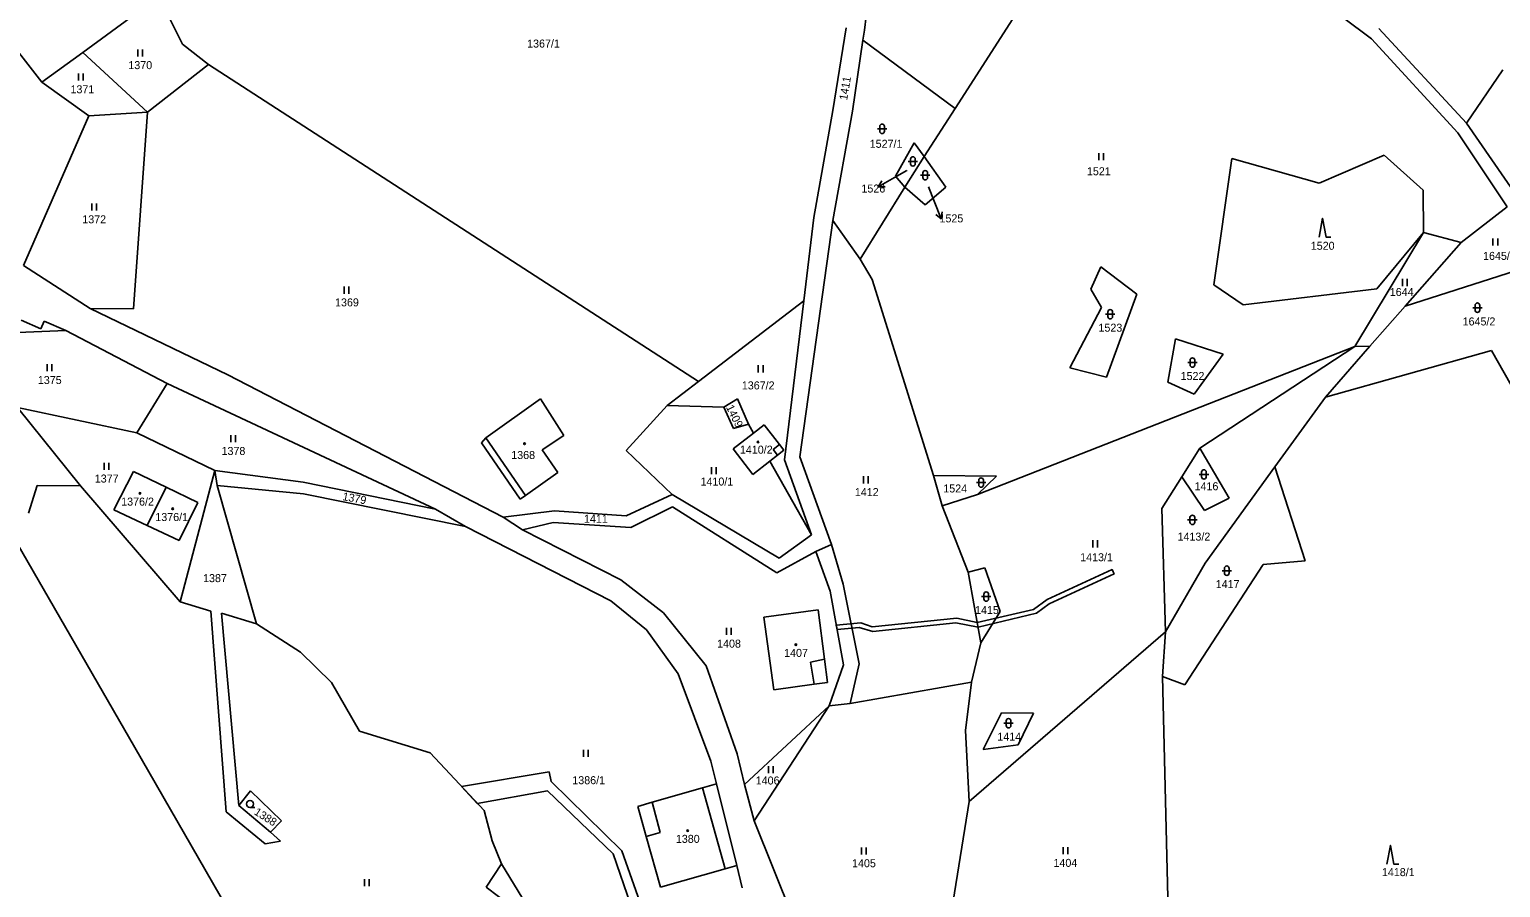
# Model space of a CAD drawing. Extents: x -670359 to -660124, y -978807 to -970072.
# Drawn here: x -669575.5 to -669263, y -978442.6 to -978260.3 of the extents above; entities that cross this region are included whole.
import ezdxf

# ---------------------------------------------------------------- set-up
doc = ezdxf.new("R2010")
doc.units = 0
for name, color, linetype in [('Hranice kat_území', 7, 'Continuous'), ('Hranice parcel', 7, 'Continuous'), ('Parcelní čísla', 7, 'Continuous'), ('Vnitřní kresba', 7, 'Continuous'), ('Věcná břemena k části', 7, 'Continuous'), ('Značky budov', 7, 'Continuous'), ('Značky kultur', 7, 'Continuous')]:
    doc.layers.add(name, color=color, linetype=linetype)

msp = doc.modelspace()

# ---------------------------------------------------------------- linework, layer by layer
at = {"layer": 'Hranice kat_území'}
for points in [[(-669579.21, -978367.53), (-669553.11, -978412.89)], [(-669553.11, -978412.89), (-669532.01, -978449.57)]]:
    msp.add_lwpolyline(points, dxfattribs=at)
at = {"layer": 'Hranice parcel'}
for p, q in [((-669411.05, -978318), (-669408.91, -978300.27)), ((-669433.38, -978335.12), (-669411.05, -978318)), ((-669411.05, -978318), (-669415.14, -978351.79))]:
    msp.add_line(p, q, dxfattribs=at)
for points in [[(-669388.24, -978177.08), (-669398.17, -978260.47)], [(-669572.87, -978271.54), (-669624.52, -978205.08)], [(-669343.73, -978222.27), (-669378.91, -978277.09)], [(-669290.44, -978262.28), (-669308.63, -978248.64)], [(-669548.02, -978253.34), (-669564.16, -978265.18)], [(-669543.01, -978263.47), (-669548.02, -978253.34)], [(-669402.01, -978259.95), (-669404.83, -978277.52)], [(-669398.17, -978260.47), (-669398.48, -978262.57)], [(-669288.9, -978260.13), (-669270.3, -978280.25)], [(-669537.45, -978267.77), (-669543.01, -978263.47)], [(-669400.67, -978277.64), (-669398.48, -978262.57)], [(-669398.48, -978262.57), (-669378.91, -978277.09)], [(-669290.44, -978262.28), (-669272.16, -978282.31)], [(-669564.16, -978265.18), (-669572.87, -978271.54)], [(-669550.44, -978277.86), (-669564.16, -978265.18)], [(-669537.45, -978267.77), (-669550.44, -978277.86)], [(-669433.38, -978335.12), (-669537.45, -978267.77)], [(-669270.3, -978280.25), (-669262.58, -978268.89)], [(-669562.88, -978278.68), (-669572.87, -978271.54)], [(-669576.72, -978310.45), (-669562.88, -978278.68)], [(-669550.44, -978277.86), (-669562.88, -978278.68)], [(-669550.44, -978277.86), (-669553.36, -978319.66)], [(-669404.83, -978277.52), (-669408.91, -978300.27)], [(-669400.67, -978277.64), (-669404.84, -978300.87)], [(-669385.48, -978287.32), (-669378.91, -978277.09)], [(-669272.16, -978282.31), (-669261.68, -978298.02)], [(-669270.3, -978280.25), (-669259.5, -978295.8)], [(-669387.61, -978284.42), (-669391.53, -978291.5)], [(-669385.48, -978287.32), (-669387.61, -978284.42)], [(-669385.48, -978287.32), (-669389.56, -978293.84)], [(-669385.48, -978287.32), (-669380.83, -978293.85)], [(-669320.09, -978287.71), (-669323.97, -978314.54)], [(-669301.57, -978292.95), (-669320.09, -978287.71)], [(-669287.74, -978287.02), (-669301.57, -978292.95)], [(-669279.5, -978294.47), (-669287.74, -978287.02)], [(-669391.53, -978291.5), (-669389.56, -978293.84)], [(-669389.56, -978293.84), (-669399.08, -978309.09)], [(-669385.27, -978297.56), (-669389.56, -978293.84)], [(-669380.83, -978293.85), (-669385.27, -978297.56)], [(-669279.43, -978303.43), (-669279.5, -978294.47)], [(-669261.68, -978298.02), (-669271.45, -978305.59)], [(-669404.84, -978300.87), (-669411.85, -978351.11)], [(-669404.84, -978300.87), (-669399.08, -978309.09)], [(-669279.43, -978303.43), (-669294.02, -978327.66)], [(-669289.32, -978315.4), (-669279.43, -978303.43)], [(-669271.45, -978305.59), (-669279.43, -978303.43)], [(-669271.45, -978305.59), (-669283.33, -978319.11)], [(-669562.62, -978319.59), (-669576.72, -978310.45)], [(-669399.08, -978309.09), (-669396.49, -978313.44)], [(-669350.08, -978315.46), (-669347.95, -978310.76)], [(-669347.95, -978310.76), (-669340.33, -978316.53)], [(-669283.33, -978319.11), (-669252.6, -978309.23)], [(-669396.49, -978313.44), (-669383.48, -978355.09)], [(-669347.8, -978319.4), (-669350.08, -978315.46)], [(-669340.33, -978316.53), (-669346.76, -978334.21)], [(-669323.97, -978314.54), (-669317.7, -978318.85)], [(-669317.7, -978318.85), (-669289.32, -978315.4)], [(-669533.35, -978333.71), (-669562.62, -978319.59)], [(-669553.36, -978319.66), (-669562.62, -978319.59)], [(-669354.5, -978332.21), (-669347.8, -978319.4)], [(-669290.81, -978327.62), (-669283.33, -978319.11)], [(-669573.09, -978323.91), (-669577.23, -978322.1)], [(-669572.37, -978322.26), (-669573.09, -978323.91)], [(-669567.79, -978324.26), (-669572.37, -978322.26)], [(-669567.79, -978324.26), (-669588.32, -978325.13)], [(-669546.24, -978335.54), (-669567.79, -978324.26)], [(-669333.72, -978335.23), (-669332.1, -978326.05)], [(-669332.1, -978326.05), (-669321.97, -978329.28)], [(-669294.02, -978327.66), (-669374.15, -978359.11)], [(-669321.97, -978329.28), (-669328.14, -978337.77)], [(-669326.9, -978349.3), (-669294.02, -978327.66)], [(-669290.81, -978327.62), (-669300.21, -978338.47)], [(-669300.21, -978338.47), (-669264.97, -978328.54)], [(-669294.02, -978327.66), (-669290.81, -978327.62)], [(-669264.97, -978328.54), (-669259.62, -978338.03)], [(-669346.76, -978334.21), (-669354.5, -978332.21)], [(-669552.68, -978345.99), (-669546.24, -978335.54)], [(-669489.22, -978362.27), (-669546.24, -978335.54)], [(-669474.91, -978363.94), (-669533.35, -978333.71)], [(-669440.07, -978340.24), (-669433.38, -978335.12)], [(-669328.14, -978337.77), (-669333.72, -978335.23)], [(-669478.57, -978347.11), (-669466.96, -978338.79)], [(-669466.96, -978338.79), (-669461.99, -978346.57)], [(-669425.09, -978338.81), (-669427.99, -978340.53)], [(-669422.75, -978344.19), (-669425.09, -978338.81)], [(-669300.21, -978338.47), (-669311.02, -978353.24)], [(-669552.68, -978345.99), (-669578, -978340.67)], [(-669578, -978340.67), (-669564.65, -978357.3)], [(-669440.07, -978340.24), (-669448.74, -978349.75)], [(-669427.99, -978340.53), (-669440.07, -978340.24)], [(-669425.96, -978345.12), (-669427.99, -978340.53)], [(-669422.75, -978344.19), (-669425.96, -978345.12)], [(-669422.75, -978344.19), (-669421.68, -978346.06)], [(-669419.44, -978344.32), (-669421.68, -978346.06)], [(-669416.17, -978348.51), (-669419.44, -978344.32)], [(-669536.12, -978354), (-669552.68, -978345.99)], [(-669479.46, -978348.14), (-669478.57, -978347.11)], [(-669471.26, -978360.14), (-669479.46, -978348.14)], [(-669461.99, -978346.57), (-669466.59, -978349.64)], [(-669421.68, -978346.06), (-669426.02, -978349.45)], [(-669466.59, -978349.64), (-669463.24, -978354.47)], [(-669448.74, -978349.75), (-669438.99, -978359.09)], [(-669426.02, -978349.45), (-669421.82, -978354.85)], [(-669418.27, -978352.06), (-669416.59, -978350.73)], [(-669416.59, -978350.73), (-669415.25, -978349.69)], [(-669415.25, -978349.69), (-669416.17, -978348.51)], [(-669411.85, -978351.11), (-669405.17, -978369.74)], [(-669330.73, -978355.34), (-669326.9, -978349.3)], [(-669326.9, -978349.3), (-669320.69, -978359.93)], [(-669557.58, -978362.41), (-669553.41, -978354.26)], [(-669553.41, -978354.26), (-669546.47, -978357.59)], [(-669536.12, -978354), (-669543.46, -978381.92)], [(-669535.59, -978357.21), (-669536.12, -978354)], [(-669536.12, -978354), (-669517.33, -978356.53)], [(-669463.24, -978354.47), (-669470.13, -978359.36)], [(-669421.82, -978354.85), (-669418.27, -978352.06)], [(-669409.39, -978367.69), (-669418.27, -978352.06)], [(-669415.14, -978351.79), (-669409.39, -978367.69)], [(-669311.02, -978353.24), (-669325.8, -978373.71)], [(-669311.02, -978353.24), (-669304.58, -978373.22)], [(-669573.85, -978357.2), (-669575.68, -978363.1)], [(-669564.65, -978357.3), (-669573.85, -978357.2)], [(-669543.46, -978381.92), (-669564.65, -978357.3)], [(-669546.47, -978357.59), (-669550.47, -978365.74)], [(-669546.47, -978357.59), (-669539.71, -978360.84)], [(-669535.59, -978357.21), (-669517.28, -978359.01)], [(-669527.26, -978386.57), (-669535.59, -978357.21)], [(-669517.33, -978356.53), (-669489.22, -978362.27)], [(-669383.48, -978355.09), (-669381.62, -978361.51)], [(-669370.11, -978355.24), (-669383.48, -978355.09)], [(-669374.15, -978359.11), (-669370.11, -978355.24)], [(-669335.02, -978362.1), (-669330.73, -978355.34)], [(-669325.92, -978362.51), (-669330.73, -978355.34)], [(-669517.28, -978359.01), (-669482.85, -978365.94)], [(-669470.13, -978359.36), (-669471.26, -978360.14)], [(-669438.99, -978359.09), (-669448.73, -978363.67)], [(-669416.24, -978372.66), (-669438.99, -978359.09)], [(-669374.15, -978359.11), (-669381.62, -978361.51)], [(-669320.69, -978359.93), (-669325.92, -978362.51)], [(-669550.47, -978365.74), (-669557.58, -978362.41)], [(-669539.71, -978360.84), (-669543.68, -978368.92)], [(-669482.85, -978365.94), (-669489.22, -978362.27)], [(-669464.01, -978362.62), (-669474.91, -978363.94)], [(-669470.77, -978366.63), (-669474.91, -978363.94)], [(-669448.73, -978363.67), (-669464.01, -978362.62)], [(-669438.94, -978361.77), (-669447.79, -978366.16)], [(-669416.76, -978375.77), (-669438.94, -978361.77)], [(-669381.62, -978361.51), (-669376.09, -978375.65)], [(-669334.2, -978388.3), (-669335.02, -978362.1)], [(-669543.68, -978368.92), (-669550.47, -978365.74)], [(-669452.04, -978381.71), (-669482.85, -978365.94)], [(-669464.27, -978365.1), (-669470.77, -978366.63)], [(-669449.91, -978377.25), (-669470.77, -978366.63)], [(-669447.79, -978366.16), (-669464.27, -978365.1)], [(-669409.39, -978367.69), (-669416.24, -978372.66)], [(-669405.17, -978369.74), (-669408.46, -978371.22)], [(-669408.46, -978371.22), (-669416.76, -978375.77)], [(-669408.46, -978371.22), (-669405.43, -978379.65)], [(-669304.58, -978373.22), (-669313.48, -978374)], [(-669372.56, -978374.73), (-669376.09, -978375.65)], [(-669376.09, -978375.65), (-669373.45, -978390.63)], [(-669369.29, -978383.96), (-669372.56, -978374.73)], [(-669325.8, -978373.71), (-669334.2, -978388.3)], [(-669313.48, -978374), (-669330.08, -978399.58)], [(-669440.86, -978384.23), (-669449.91, -978377.25)], [(-669536.99, -978383.91), (-669543.46, -978381.92)], [(-669444.42, -978387.87), (-669452.04, -978381.71)], [(-669405.43, -978379.65), (-669402.63, -978395.28)], [(-669533.68, -978426.58), (-669536.99, -978383.91)], [(-669527.26, -978386.57), (-669534.68, -978384.33)], [(-669534.68, -978384.33), (-669531.02, -978425.17)], [(-669431.77, -978395.52), (-669440.86, -978384.23)], [(-669419.5, -978385.18), (-669407.95, -978383.66)], [(-669417.42, -978400.64), (-669419.5, -978385.18)], [(-669407.95, -978383.66), (-669406.62, -978394.11)], [(-669373.45, -978390.63), (-669369.29, -978383.96)], [(-669517.95, -978392.59), (-669527.26, -978386.57)], [(-669437.71, -978397.22), (-669444.42, -978387.87)], [(-669334.2, -978388.3), (-669375.91, -978424.37)], [(-669334.86, -978397.77), (-669334.2, -978388.3)], [(-669373.45, -978390.63), (-669375.38, -978399.01)], [(-669511.3, -978399.06), (-669517.95, -978392.59)], [(-669406.62, -978394.11), (-669405.99, -978399.06)], [(-669430.79, -978415.77), (-669437.71, -978397.22)], [(-669425.17, -978414.23), (-669431.77, -978395.52)], [(-669402.63, -978395.28), (-669405.61, -978404.04)], [(-669330.08, -978399.58), (-669334.86, -978397.77)], [(-669334.86, -978397.77), (-669333.58, -978450.65)], [(-669505.4, -978409.44), (-669511.3, -978399.06)], [(-669408.84, -978399.45), (-669417.42, -978400.64)], [(-669405.99, -978399.06), (-669408.84, -978399.45)], [(-669375.38, -978399.01), (-669401.2, -978403.53)], [(-669376.69, -978409.24), (-669375.38, -978399.01)], [(-669405.61, -978404.04), (-669423.63, -978420.73)], [(-669405.61, -978404.04), (-669421.55, -978428.43)], [(-669401.2, -978403.53), (-669405.61, -978404.04)], [(-669372.97, -978413.27), (-669369.04, -978405.48)], [(-669369.04, -978405.48), (-669362.24, -978405.55)], [(-669362.24, -978405.55), (-669365.51, -978412.32)], [(-669490.4, -978414.01), (-669505.4, -978409.44)], [(-669375.91, -978424.37), (-669376.69, -978409.24)], [(-669365.51, -978412.32), (-669372.97, -978413.27)], [(-669478.93, -978426.29), (-669490.4, -978414.01)], [(-669429.59, -978420.58), (-669430.79, -978415.77)], [(-669423.63, -978420.73), (-669425.17, -978414.23)], [(-669531.02, -978425.17), (-669528.51, -978422.07)], [(-669528.51, -978422.07), (-669521.93, -978428.46)], [(-669432.53, -978421.43), (-669443.21, -978424.51)], [(-669429.59, -978420.58), (-669432.53, -978421.43)], [(-669425.28, -978437.98), (-669429.59, -978420.58)], [(-669421.55, -978428.43), (-669423.63, -978420.73)], [(-669524.28, -978430.84), (-669531.02, -978425.17)], [(-669477.23, -978432.7), (-669478.93, -978426.29)], [(-669443.21, -978424.51), (-669446.28, -978425.4)], [(-669446.28, -978425.4), (-669444.48, -978431.78)], [(-669375.91, -978424.37), (-669381.83, -978461.38)], [(-669525.43, -978433.38), (-669533.68, -978426.58)], [(-669521.93, -978428.46), (-669524.28, -978430.84)], [(-669413.37, -978448.91), (-669421.55, -978428.43)], [(-669524.28, -978430.84), (-669522.14, -978432.78)], [(-669444.48, -978431.78), (-669441.44, -978442.57)], [(-669522.14, -978432.78), (-669525.43, -978433.38)], [(-669475.2, -978437.61), (-669477.23, -978432.7)], [(-669478.46, -978442.53), (-669475.2, -978437.61)], [(-669475.2, -978437.61), (-669469.93, -978446.3)], [(-669441.44, -978442.57), (-669427.75, -978438.68)], [(-669427.75, -978438.68), (-669425.28, -978437.98)], [(-669424.11, -978442.72), (-669425.28, -978437.98)], [(-669470.64, -978448.51), (-669478.46, -978442.53)]]:
    msp.add_lwpolyline(points, dxfattribs=at)
at = {"layer": 'Parcelní čísla'}
for p, q in [((-669389.18, -978290.28), (-669391.77, -978291.77)), ((-669393.74, -978293.76), (-669395.24, -978293.76)), ((-669384.52, -978293.78), (-669383.32, -978296.81)), ((-669381.63, -978299.04), (-669381.84, -978300.53))]:
    msp.add_line(p, q, dxfattribs=at)
for points in [[(-669391.77, -978291.77), (-669395.24, -978293.76), (-669394.48, -978292.46)], [(-669383.32, -978296.81), (-669381.84, -978300.53), (-669383.02, -978299.6)]]:
    msp.add_lwpolyline(points, dxfattribs=at)
at = {"layer": 'Vnitřní kresba'}
for points in [[(-669478.57, -978347.11), (-669470.13, -978359.36)], [(-669416.17, -978348.51), (-669417.51, -978349.55)], [(-669417.51, -978349.55), (-669416.59, -978350.73)], [(-669402.69, -978378.16), (-669405.17, -978369.74)], [(-669399.27, -978395.07), (-669402.69, -978378.16)], [(-669409.59, -978394.72), (-669406.62, -978394.11)], [(-669408.84, -978399.45), (-669409.59, -978394.72)], [(-669401.2, -978403.53), (-669399.27, -978395.07)], [(-669432.53, -978421.43), (-669427.75, -978438.68)], [(-669443.21, -978424.51), (-669441.55, -978430.93)], [(-669441.55, -978430.93), (-669444.48, -978431.78)]]:
    msp.add_lwpolyline(points, dxfattribs=at)
at = {"layer": 'Věcná břemena k části'}
for p, q in [((-669483.73, -978421.15), (-669465.12, -978418.04)), ((-669465.12, -978418.04), (-669464.66, -978420.07)), ((-669464.66, -978420.07), (-669449.65, -978434.83)), ((-669480.37, -978424.75), (-669483.73, -978421.15)), ((-669465.46, -978422.11), (-669480.37, -978424.75)), ((-669451.54, -978435.49), (-669465.46, -978422.11)), ((-669447.74, -978446.35), (-669451.54, -978435.49)), ((-669449.65, -978434.83), (-669445.86, -978445.69))]:
    msp.add_line(p, q, dxfattribs=at)
for points in [[(-669404.14, -978386.88), (-669398.94, -978386.4), (-669396.5, -978387.26), (-669378.51, -978385.42), (-669374.21, -978386.3), (-669362.22, -978383.56), (-669359.32, -978381.42), (-669346.46, -978375.5), (-669345.55, -978375.08), (-669345.34, -978375.53), (-669345.14, -978375.99), (-669346.04, -978376.4), (-669358.9, -978382.32), (-669361.64, -978384.36), (-669373.99, -978387.28), (-669378.71, -978386.4), (-669396.4, -978388.26), (-669399.26, -978387.36), (-669403.96, -978387.83)], [(-669403.96, -978387.83), (-669404.14, -978386.88)]]:
    msp.add_lwpolyline(points, dxfattribs=at)
at = {"layer": 'Značky budov'}
for centre in [(-669470.33, -978348.33), (-669420.76, -978347.95), (-669552, -978358.88), (-669545.07, -978362.16), (-669412.71, -978391.03), (-669435.7, -978430.54)]:
    msp.add_circle(centre, 0.175, dxfattribs=at)
at = {"layer": 'Značky kultur'}
for p, q in [((-669552.48, -978264.54), (-669552.48, -978266.04)), ((-669551.48, -978266.04), (-669551.48, -978264.54)), ((-669565.09, -978269.67), (-669565.09, -978271.17)), ((-669564.09, -978271.17), (-669564.09, -978269.67)), ((-669395.39, -978281.43), (-669393.39, -978281.43)), ((-669394.89, -978280.93), (-669394.89, -978281.93)), ((-669393.89, -978280.93), (-669393.89, -978281.93)), ((-669388.86, -978288.35), (-669386.86, -978288.35)), ((-669388.36, -978287.85), (-669388.36, -978288.85)), ((-669387.36, -978287.85), (-669387.36, -978288.85)), ((-669348.4, -978286.6), (-669348.4, -978288.1)), ((-669347.4, -978288.1), (-669347.4, -978286.6)), ((-669386.25, -978291.29), (-669384.25, -978291.29)), ((-669385.75, -978290.79), (-669385.75, -978291.79)), ((-669384.75, -978290.79), (-669384.75, -978291.79)), ((-669562.26, -978297.3), (-669562.26, -978298.8)), ((-669561.26, -978298.8), (-669561.26, -978297.3)), ((-669264.66, -978304.74), (-669264.66, -978306.24)), ((-669263.66, -978306.24), (-669263.66, -978304.74)), ((-669283.89, -978313.33), (-669283.89, -978314.83)), ((-669282.89, -978314.83), (-669282.89, -978313.33)), ((-669508.62, -978314.95), (-669508.62, -978316.45)), ((-669507.62, -978316.45), (-669507.62, -978314.95)), ((-669268.97, -978319.43), (-669266.97, -978319.43)), ((-669268.47, -978318.93), (-669268.47, -978319.93)), ((-669267.47, -978318.93), (-669267.47, -978319.93)), ((-669346.95, -978320.83), (-669344.95, -978320.83)), ((-669346.45, -978320.33), (-669346.45, -978321.33)), ((-669345.45, -978320.33), (-669345.45, -978321.33)), ((-669571.7, -978331.45), (-669571.7, -978332.95)), ((-669570.7, -978332.95), (-669570.7, -978331.45)), ((-669420.69, -978331.67), (-669420.69, -978333.17)), ((-669419.69, -978333.17), (-669419.69, -978331.67)), ((-669329.5, -978331.09), (-669327.5, -978331.09)), ((-669329, -978330.59), (-669329, -978331.59)), ((-669328, -978330.59), (-669328, -978331.59)), ((-669532.69, -978346.52), (-669532.69, -978348.02)), ((-669531.69, -978348.02), (-669531.69, -978346.52)), ((-669559.61, -978352.38), (-669559.61, -978353.88)), ((-669558.61, -978353.88), (-669558.61, -978352.38)), ((-669430.65, -978353.31), (-669430.65, -978354.81)), ((-669429.65, -978354.81), (-669429.65, -978353.31)), ((-669326.54, -978354.35), (-669326.54, -978355.35)), ((-669325.54, -978354.35), (-669325.54, -978355.35)), ((-669398.33, -978355.26), (-669398.33, -978356.76)), ((-669397.33, -978356.76), (-669397.33, -978355.26)), ((-669374.38, -978356.58), (-669372.38, -978356.58)), ((-669373.88, -978356.08), (-669373.88, -978357.08)), ((-669372.88, -978356.08), (-669372.88, -978357.08)), ((-669327.04, -978354.85), (-669325.04, -978354.85)), ((-669329.51, -978364.52), (-669327.51, -978364.52)), ((-669329.01, -978364.02), (-669329.01, -978365.02)), ((-669328.01, -978364.02), (-669328.01, -978365.02)), ((-669349.62, -978368.85), (-669349.62, -978370.35)), ((-669348.62, -978370.35), (-669348.62, -978368.85)), ((-669322.19, -978375.31), (-669320.19, -978375.31)), ((-669321.69, -978374.81), (-669321.69, -978375.81)), ((-669320.69, -978374.81), (-669320.69, -978375.81)), ((-669373.29, -978380.82), (-669371.29, -978380.82)), ((-669372.79, -978380.32), (-669372.79, -978381.32)), ((-669371.79, -978380.32), (-669371.79, -978381.32)), ((-669427.44, -978387.46), (-669427.44, -978388.96)), ((-669426.44, -978388.96), (-669426.44, -978387.46)), ((-669368.04, -978407.23), (-669368.04, -978408.23)), ((-669367.04, -978407.23), (-669367.04, -978408.23)), ((-669368.54, -978407.73), (-669366.54, -978407.73)), ((-669457.81, -978413.34), (-669457.81, -978414.84)), ((-669456.81, -978414.84), (-669456.81, -978413.34)), ((-669418.52, -978416.84), (-669418.52, -978418.34)), ((-669417.52, -978418.34), (-669417.52, -978416.84)), ((-669528.65, -978425.63), (-669527.65, -978425.63)), ((-669398.78, -978434.12), (-669398.78, -978435.62)), ((-669397.78, -978435.62), (-669397.78, -978434.12)), ((-669355.96, -978434.04), (-669355.96, -978435.54)), ((-669354.96, -978435.54), (-669354.96, -978434.04)), ((-669504.32, -978440.85), (-669504.32, -978442.35)), ((-669503.32, -978442.35), (-669503.32, -978440.85))]:
    msp.add_line(p, q, dxfattribs=at)
for points in [[(-669301.61, -978304.42), (-669300.86, -978300.42), (-669300.11, -978304.42), (-669299.11, -978304.42)], [(-669287.19, -978437.69), (-669286.44, -978433.69), (-669285.69, -978437.69), (-669284.69, -978437.69)]]:
    msp.add_lwpolyline(points, dxfattribs=at)
for centre, radius in [((-669470.33, -978348.33), 0.175), ((-669420.76, -978347.95), 0.175), ((-669552, -978358.88), 0.175), ((-669545.07, -978362.16), 0.175), ((-669412.71, -978391.03), 0.175), ((-669528.65, -978424.88), 0.75), ((-669435.7, -978430.54), 0.175)]:
    msp.add_circle(centre, radius, dxfattribs=at)
for centre, start, end in [((-669394.39, -978280.93), 0, 180), ((-669394.39, -978281.93), 180, 0), ((-669387.86, -978287.85), 0, 180), ((-669387.86, -978288.85), 180, 0), ((-669385.25, -978290.79), 0, 180), ((-669385.25, -978291.79), 180, 0), ((-669345.95, -978320.33), 0, 180), ((-669267.97, -978318.93), 0, 180), ((-669267.97, -978319.93), 180, 0), ((-669345.95, -978321.33), 180, 0), ((-669328.5, -978330.59), 0, 180), ((-669328.5, -978331.59), 180, 0), ((-669326.04, -978354.35), 0, 180), ((-669373.38, -978356.08), 0, 180), ((-669373.38, -978357.08), 180, 0), ((-669326.04, -978355.35), 180, 0), ((-669328.51, -978364.02), 0, 180), ((-669328.51, -978365.02), 180, 0), ((-669321.19, -978374.81), 0, 180), ((-669321.19, -978375.81), 180, 0), ((-669372.29, -978380.32), 0, 180), ((-669372.29, -978381.32), 180, 0), ((-669367.54, -978407.23), 0, 180), ((-669367.54, -978408.23), 180, 0)]:
    msp.add_arc(centre, 0.5, start, end, dxfattribs=at)

# ---------------------------------------------------------------- texts
at = {"layer": 'Parcelní čísla'}
for s, height, p in [('1367/1', 1.7, (-669469.79, -978264.16)), ('1370', 1.7, (-669554.48, -978268.74)), ('1371', 1.7, (-669566.77, -978273.87)), ('1527/1', 1.7, (-669397.03, -978285.45)), ('1526', 0.1, (-669389.18, -978290.28)), ('1521', 1.7, (-669350.9, -978291.29)), ('1526', 1.7, (-669398.79, -978294.96)), ('1525', 0.1, (-669384.52, -978293.78)), ('1372', 1.7, (-669564.26, -978301.5)), ('1525', 1.7, (-669382.21, -978301.3)), ('1520', 1.7, (-669303.36, -978307.12)), ('1645/1', 1.7, (-669266.77, -978309.27)), ('1644', 1.7, (-669286.58, -978316.94)), ('1369', 1.7, (-669510.58, -978319.15)), ('1523', 1.7, (-669348.45, -978324.53)), ('1645/2', 1.7, (-669271.11, -978323.2)), ('1375', 1.7, (-669573.7, -978335.65)), ('1367/2', 1.7, (-669424.19, -978336.79)), ('1522', 1.7, (-669331, -978334.79)), ('1378', 1.7, (-669534.69, -978350.72)), ('1368', 1.7, (-669473.16, -978351.58)), ('1410/2', 1.7, (-669424.6, -978350.45)), ('1377', 1.7, (-669561.61, -978356.58)), ('1410/1', 1.7, (-669432.96, -978357.22)), ('1524', 1.7, (-669381.4, -978358.69)), ('1416', 1.7, (-669328.04, -978358.22)), ('1376/2', 1.7, (-669556, -978361.48)), ('1412', 1.7, (-669400.19, -978359.46)), ('1376/1', 1.7, (-669548.75, -978364.76)), ('1411', 1.7, (-669457.72, -978365.12)), ('1413/2', 1.7, (-669331.65, -978368.92)), ('1413/1', 1.7, (-669352.33, -978373.3)), ('1387', 1.7, (-669538.61, -978377.74)), ('1417', 1.7, (-669323.55, -978379.01)), ('1415', 1.7, (-669374.65, -978384.52)), ('1408', 1.7, (-669429.44, -978391.66)), ('1407', 1.7, (-669415.21, -978393.63)), ('1414', 1.7, (-669369.93, -978411.43)), ('1386/1', 1.7, (-669460.19, -978420.68)), ('1406', 1.7, (-669421.24, -978420.74)), ('1380', 1.7, (-669438.2, -978433.14)), ('1405', 1.7, (-669400.78, -978438.32)), ('1404', 1.7, (-669358, -978438.24)), ('1418/1', 1.7, (-669288.25, -978440.21))]:
    msp.add_text(s, height=height, dxfattribs=at).set_placement(p)
for s, rotation, p in [('1411', 80.4763, (-669401.83, -978275.43)), ('1409', 296.1861, (-669427.6, -978340.56)), ('1379', 349.5401, (-669509.09, -978360.3)), ('1388', 327.6927, (-669527.92, -978426.98))]:
    msp.add_text(s, height=1.7, rotation=rotation, dxfattribs=at).set_placement(p)

doc.saveas('drawing.dxf')
